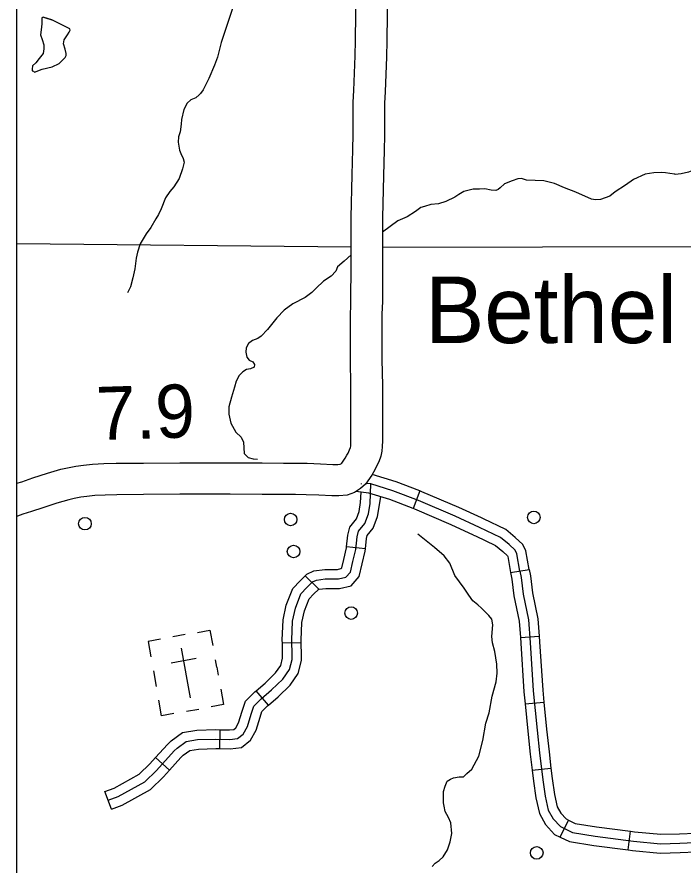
# Model space of a CAD drawing. Extents: x 1369979 to 1371646, y 379997 to 381064.
# Drawn here: x 1370544.5 to 1370606.5, y 380305.4 to 380384.3 of the extents above; entities that cross this region are included whole.
import ezdxf

# ---------------------------------------------------------------- set-up
doc = ezdxf.new("R2010")
doc.units = 0
doc.layers.add('R_Border Notes', color=7, linetype='Continuous')
doc.layers.add('R_No Plot', color=7, linetype='Continuous')

msp = doc.modelspace()

# ---------------------------------------------------------------- linework, layer by layer
at = {"layer": 'R_Border Notes'}
for p, q in [((1370582.009, 380340.244), (1370581.378, 380338.604)), ((1370587.727, 380337.738), (1370587.727, 380337.738)), ((1370576.925, 380334.851), (1370575.178, 380335.045)), ((1370590.426, 380332.649), (1370592.16, 380332.936)), ((1370572.582, 380331.117), (1370571.338, 380332.36)), ((1370560.164, 380326.878), (1370559.011, 380326.668)), ((1370591.353, 380326.621), (1370593.106, 380326.751)), ((1370559.791, 380325.619), (1370560.63, 380321.007)), ((1370570.959, 380326.112), (1370569.202, 380326.079)), ((1370558.847, 380324.256), (1370561.164, 380324.678)), ((1370563.093, 380323.838), (1370562.963, 380324.548)), ((1370563.093, 380323.838), (1370563.226, 380323.107)), ((1370557.199, 380323.499), (1370557.461, 380322.058)), ((1370560.21, 380323.313), (1370560.21, 380323.313)), ((1370560.21, 380323.313), (1370560.21, 380323.313)), ((1370567.903, 380320.309), (1370566.753, 380321.638)), ((1370560.27, 380319.751), (1370561.422, 380319.96)), ((1370591.792, 380320.428), (1370593.542, 380320.601)), ((1370563.374, 380316.276), (1370563.409, 380318.034)), ((1370558.699, 380314.277), (1370557.398, 380315.459)), ((1370592.448, 380314.262), (1370594.195, 380314.462)), ((1370553.286, 380310.639), (1370552.689, 380312.292)), ((1370595.055, 380308.048), (1370595.827, 380309.627)), ((1370601.375, 380306.844), (1370601.604, 380308.586))]:
    msp.add_line(p, q, dxfattribs=at)
for points in [[(1370575.58, 380357.913), (1370575.596, 380361.239), (1370575.604, 380365.69), (1370575.683, 380369.665), (1370575.754, 380372.023), (1370575.792, 380373.399), (1370575.793, 380376.406), (1370575.841, 380377.504), (1370575.974, 380380.734), (1370576.004, 380382.172), (1370576.004, 380382.412), (1370576.068, 380386.386), (1370576.146, 380388.319), (1370576.169, 380389.662), (1370576.177, 380390.743)], [(1370579.107, 380390.722), (1370579.099, 380389.626), (1370579.075, 380388.235), (1370578.997, 380386.303), (1370578.934, 380382.389), (1370578.934, 380382.141), (1370578.902, 380380.642), (1370578.768, 380377.379), (1370578.722, 380376.341), (1370578.722, 380373.358), (1370578.682, 380371.938), (1370578.612, 380369.592), (1370578.534, 380365.658), (1370578.526, 380361.23), (1370578.51, 380357.899)], [(1370565.47, 380387.318), (1370565.127, 380386.498), (1370564.697, 380385.551), (1370564.367, 380384.591), (1370563.852, 380382.999), (1370563.508, 380381.981), (1370563.164, 380380.604), (1370562.877, 380379.873), (1370562.362, 380378.625)], [(1370547.751, 380384.08), (1370546.942, 380384.32), (1370546.799, 380384.262), (1370546.799, 380383.703), (1370546.741, 380383.144), (1370546.698, 380382.671), (1370546.842, 380382.255), (1370546.985, 380381.753), (1370546.999, 380381.394), (1370546.928, 380380.95), (1370546.57, 380380.477), (1370546.24, 380380.075), (1370545.954, 380379.803), (1370545.911, 380379.502), (1370545.911, 380379.329), (1370546.025, 380379.301), (1370546.125, 380379.215), (1370546.842, 380379.487), (1370547.787, 380379.702), (1370548.418, 380380.018), (1370548.976, 380380.577), (1370549.077, 380380.749), (1370549.062, 380380.95), (1370548.976, 380381.337), (1370548.833, 380381.839), (1370548.89, 380382.212), (1370549.191, 380382.671), (1370549.349, 380382.943), (1370549.449, 380383.115), (1370549.42, 380383.244), (1370547.751, 380384.08)], [(1370546.972, 380384.318), (1370547.822, 380384.057), (1370549.384, 380383.276)], [(1370562.362, 380378.625), (1370561.82, 380377.561), (1370561.591, 380377.217), (1370561.462, 380377.117), (1370561.132, 380376.816), (1370560.674, 380376.629), (1370560.33, 380376.342), (1370560.044, 380375.754), (1370559.8, 380374.822), (1370559.771, 380374.364), (1370559.685, 380373.661), (1370559.528, 380373.202), (1370559.499, 380372.686), (1370559.628, 380371.94), (1370559.757, 380371.639), (1370559.972, 380371.194), (1370560.072, 380370.846)], [(1370560.072, 380370.846), (1370559.9, 380370.215), (1370559.599, 380369.326), (1370559.098, 380368.552), (1370558.726, 380368.121), (1370558.324, 380367.519), (1370557.909, 380366.501), (1370557.665, 380365.956), (1370557.436, 380365.569), (1370556.949, 380364.752), (1370556.519, 380364.164), (1370556.247, 380363.705), (1370555.961, 380363.246), (1370555.731, 380362.472)], [(1370611.682, 380369.273), (1370610.276, 380369.406), (1370609.358, 380369.673), (1370608.973, 380369.851), (1370608.485, 380370.206), (1370608.056, 380370.251), (1370607.479, 380370.088), (1370607.02, 380369.895), (1370606.324, 380369.747), (1370605.777, 380369.688), (1370605.732, 380369.732), (1370605.259, 380369.777), (1370604.874, 380369.851), (1370604.474, 380369.866), (1370603.779, 380369.851), (1370602.979, 380369.732), (1370601.899, 380369.229), (1370601.129, 380368.695), (1370600.182, 380368.073), (1370599.694, 380367.688), (1370598.82, 380367.377)], [(1370591.927, 380369.169), (1370591.457, 380369.318), (1370591.117, 380369.273), (1370590.584, 380369.095), (1370589.874, 380368.814), (1370589.459, 380368.444), (1370589.297, 380368.31), (1370589.075, 380368.192), (1370588.645, 380368.221), (1370588.039, 380368.369)], [(1370598.82, 380367.377), (1370598.35, 380367.347), (1370597.965, 380367.407), (1370596.529, 380368.058), (1370595.449, 380368.444), (1370594.546, 380368.843), (1370593.525, 380369.095), (1370591.927, 380369.169)], [(1370588.039, 380368.369), (1370587.552, 380368.325), (1370586.96, 380368.325), (1370586.101, 380368.118), (1370585.613, 380367.821), (1370585.243, 380367.57), (1370584.414, 380367.17), (1370583.733, 380366.962), (1370583.023, 380366.903), (1370582.446, 380366.725), (1370582.09, 380366.607)], [(1370582.09, 380366.607), (1370581.602, 380366.236), (1370580.818, 380365.762), (1370579.959, 380365.377), (1370578.531, 380364.332)], [(1370544.495, 380363.267), (1370575.599, 380362.946)], [(1370555.731, 380362.472), (1370555.602, 380361.912), (1370555.474, 380360.909), (1370555.287, 380360.091), (1370555.058, 380359.245), (1370554.786, 380358.672)], [(1370578.529, 380362.933), (1370608.293, 380362.985)], [(1370575.598, 380362.213), (1370574.946, 380361.62), (1370574.325, 380361.102)], [(1370574.325, 380361.102), (1370574.163, 380360.693), (1370573.749, 380360.234), (1370573.024, 380359.775), (1370572.358, 380359.123), (1370571.929, 380358.708), (1370571.322, 380358.234), (1370570.167, 380357.671), (1370569.368, 380357.064), (1370568.673, 380356.353), (1370567.829, 380355.256)], [(1370575.58, 380350.002), (1370575.541, 380352.467), (1370575.541, 380353.653), (1370575.533, 380355.238), (1370575.541, 380356.153), (1370575.541, 380356.765), (1370575.565, 380357.382), (1370575.581, 380357.946)], [(1370578.509, 380357.866), (1370578.493, 380357.284), (1370578.471, 380356.707), (1370578.471, 380356.14), (1370578.463, 380355.233), (1370578.471, 380353.66), (1370578.471, 380352.49), (1370578.51, 380350.049)], [(1370567.829, 380355.256), (1370567.24, 380354.642), (1370566.914, 380354.434), (1370566.411, 380354.242), (1370566.056, 380353.96), (1370565.834, 380353.575), (1370565.804, 380353.16), (1370565.908, 380352.686), (1370566.1, 380352.427)], [(1370566.1, 380352.427), (1370566.441, 380352.249), (1370566.618, 380352.012), (1370566.589, 380351.76), (1370566.234, 380351.612), (1370565.864, 380351.538), (1370565.523, 380351.319), (1370565.168, 380350.99), (1370564.887, 380350.457), (1370564.754, 380349.909), (1370564.472, 380348.961), (1370564.221, 380348.072), (1370564.206, 380347.39), (1370564.398, 380346.561), (1370564.872, 380345.731), (1370565.36, 380345.242), (1370565.568, 380344.783), (1370565.627, 380344.265)], [(1370578.51, 380350.032), (1370578.518, 380348.18), (1370578.51, 380346.185), (1370578.518, 380344.914), (1370578.5, 380344.385), (1370578.464, 380343.953), (1370578.352, 380343.492), (1370578.178, 380342.97), (1370577.945, 380342.484), (1370577.802, 380342.198), (1370577.538, 380341.724), (1370576.934, 380340.867), (1370576.486, 380340.463), (1370575.907, 380340.095), (1370575.231, 380339.843), (1370574.449, 380339.783), (1370573.817, 380339.792), (1370572.601, 380339.848), (1370571.431, 380339.902), (1370570.413, 380339.917), (1370569.302, 380339.917)], [(1370569.302, 380342.847), (1370570.435, 380342.847), (1370571.521, 380342.83), (1370572.736, 380342.774), (1370573.906, 380342.72), (1370574.358, 380342.714), (1370574.595, 380342.732), (1370574.706, 380342.803), (1370574.729, 380342.823), (1370575.054, 380343.286), (1370575.211, 380343.566), (1370575.313, 380343.771), (1370575.457, 380344.071), (1370575.534, 380344.303), (1370575.563, 380344.423), (1370575.574, 380344.557), (1370575.588, 380344.955), (1370575.58, 380346.181), (1370575.588, 380348.18), (1370575.58, 380350.019)], [(1370565.627, 380344.265), (1370565.656, 380343.724), (1370566.026, 380343.354), (1370566.485, 380343.25), (1370566.9, 380343.206)], [(1370544.495, 380340.971), (1370544.956, 380341.111), (1370545.973, 380341.46), (1370547.345, 380341.902), (1370548.577, 380342.266), (1370549.199, 380342.407), (1370549.983, 380342.562), (1370550.681, 380342.649), (1370551.525, 380342.733), (1370552.573, 380342.791), (1370553.739, 380342.823), (1370556.261, 380342.839), (1370559.648, 380342.87), (1370564.363, 380342.87), (1370567.325, 380342.855), (1370569.308, 380342.847)], [(1370582.009, 380340.244), (1370579.783, 380341.101), (1370577.567, 380341.775)], [(1370559.126, 380316.054), (1370559.413, 380316.329), (1370560.246, 380316.928), (1370561.313, 380317.11), (1370563.004, 380317.163), (1370564.306, 380317.137), (1370565.034, 380317.215), (1370565.555, 380317.631), (1370565.945, 380318.335), (1370566.284, 380319.481), (1370566.536, 380320.218), (1370567.239, 380320.896), (1370568.202, 380321.729), (1370569.243, 380322.745), (1370569.867, 380323.631), (1370570.101, 380324.569), (1370570.101, 380324.954), (1370570.075, 380326.361), (1370570.153, 380328.133), (1370570.414, 380329.357), (1370570.934, 380330.686), (1370571.481, 380331.259), (1370572.001, 380331.78), (1370572.392, 380331.962), (1370573.198, 380332.066), (1370574.422, 380332.066), (1370575.124, 380332.223), (1370575.541, 380332.692), (1370575.775, 380333.681), (1370576.035, 380334.802), (1370576.165, 380335.974), (1370576.295, 380336.495), (1370576.868, 380337.224), (1370577.206, 380338.11), (1370577.362, 380339.074), (1370577.44, 380340.895)], [(1370576.56, 380340.877), (1370576.562, 380340.933)], [(1370591.293, 380332.792), (1370591.026, 380334.408), (1370590.869, 380334.747), (1370590.297, 380335.268), (1370589.516, 380335.919), (1370587.538, 380336.857), (1370585.274, 380337.899), (1370581.865, 380339.358), (1370579.496, 380340.27), (1370577.44, 380340.895), (1370576.994, 380340.952)], [(1370569.296, 380339.917), (1370567.311, 380339.925), (1370564.356, 380339.941), (1370559.661, 380339.941), (1370556.284, 380339.909), (1370553.789, 380339.894), (1370552.695, 380339.863), (1370551.75, 380339.811), (1370551.008, 380339.738), (1370550.45, 380339.668), (1370549.806, 380339.54), (1370549.316, 380339.43), (1370548.21, 380339.103), (1370546.898, 380338.68), (1370545.859, 380338.323), (1370545.046, 380338.076), (1370544.555, 380337.917), (1370544.495, 380337.892)], [(1370575.178, 380335.045), (1370575.298, 380336.13), (1370575.488, 380336.89), (1370576.094, 380337.662), (1370576.353, 380338.34), (1370576.487, 380339.163), (1370576.528, 380340.126)], [(1370581.378, 380338.604), (1370579.21, 380339.438), (1370577.255, 380340.033), (1370576.052, 380340.187)], [(1370576.925, 380334.851), (1370577.032, 380335.818), (1370577.103, 380336.1), (1370577.641, 380336.786), (1370578.059, 380337.881), (1370578.354, 380339.699)], [(1370587.727, 380337.738), (1370585.631, 380338.702), (1370582.196, 380340.172), (1370582.009, 380340.244)], [(1370586.992, 380336.141), (1370584.917, 380337.096), (1370581.534, 380338.544), (1370581.378, 380338.604)], [(1370592.16, 380332.936), (1370591.873, 380334.669), (1370591.593, 380335.277), (1370590.874, 380335.931), (1370589.993, 380336.666), (1370587.91, 380337.653), (1370587.727, 380337.738)], [(1370585.254, 380332.383), (1370584.788, 380333.52), (1370584.255, 380334.226), (1370583.377, 380334.976), (1370581.808, 380336.229)], [(1370586.992, 380336.141), (1370587.166, 380336.061), (1370589.039, 380335.173), (1370589.719, 380334.605), (1370590.146, 380334.217), (1370590.178, 380334.148), (1370590.426, 380332.649)], [(1370571.338, 380332.36), (1370571.489, 380332.51), (1370572.143, 380332.816), (1370573.142, 380332.945), (1370574.325, 380332.945), (1370574.656, 380333.019), (1370574.736, 380333.109), (1370574.919, 380333.882), (1370575.167, 380334.95), (1370575.178, 380335.045)], [(1370572.514, 380331.049), (1370572.64, 380331.108), (1370573.255, 380331.187), (1370574.518, 380331.187), (1370575.593, 380331.426), (1370576.345, 380332.274), (1370576.631, 380333.481), (1370576.903, 380334.653), (1370576.925, 380334.851)], [(1370590.425, 380332.649), (1370590.556, 380332.045), (1370590.751, 380330.495), (1370591.241, 380328.12), (1370591.353, 380326.621)], [(1370591.293, 380332.792), (1370591.423, 380332.193), (1370591.619, 380330.639), (1370592.113, 380328.242), (1370592.27, 380326.147), (1370592.556, 380321.641), (1370592.915, 380318.004), (1370593.149, 380315.868), (1370593.436, 380313.367), (1370593.67, 380311.856), (1370593.956, 380310.553), (1370594.398, 380309.746), (1370595.075, 380309.016), (1370596.194, 380308.469), (1370598.328, 380308.131), (1370601.894, 380307.662), (1370604.392, 380307.427), (1370606.188, 380307.479), (1370608.244, 380307.558)], [(1370592.161, 380332.936), (1370592.29, 380332.342), (1370592.487, 380330.783), (1370592.986, 380328.364), (1370593.106, 380326.751)], [(1370569.202, 380326.079), (1370569.196, 380326.372), (1370569.279, 380328.244), (1370569.569, 380329.61), (1370570.179, 380331.167), (1370570.852, 380331.873), (1370571.338, 380332.36)], [(1370586.112, 380331.2), (1370585.254, 380332.383)], [(1370570.959, 380326.112), (1370570.955, 380326.35), (1370571.028, 380328.021), (1370571.258, 380329.104), (1370571.69, 380330.204), (1370572.11, 380330.645), (1370572.582, 380331.117)], [(1370588.992, 380325.321), (1370588.747, 380326.105), (1370588.689, 380326.696), (1370588.804, 380327.777), (1370588.704, 380328.31), (1370588.416, 380328.67), (1370588.07, 380329.016), (1370587.739, 380329.347), (1370587.394, 380329.65), (1370586.933, 380330.01), (1370586.559, 380330.538), (1370586.112, 380331.2)], [(1370561.31, 380327.087), (1370562.463, 380327.297), (1370562.725, 380325.855)], [(1370557.851, 380326.457), (1370556.698, 380326.247), (1370556.961, 380324.806)], [(1370591.353, 380326.621), (1370591.393, 380326.087), (1370591.68, 380321.57), (1370591.792, 380320.428)], [(1370593.106, 380326.751), (1370593.146, 380326.208), (1370593.432, 380321.712), (1370593.542, 380320.601)], [(1370566.753, 380321.638), (1370567.607, 380322.377), (1370568.571, 380323.318), (1370569.054, 380324.003), (1370569.223, 380324.677), (1370569.223, 380324.946), (1370569.202, 380326.079)], [(1370567.903, 380320.309), (1370568.797, 380321.082), (1370569.914, 380322.173), (1370570.68, 380323.259), (1370570.98, 380324.461), (1370570.98, 380324.963), (1370570.959, 380326.112)], [(1370588.142, 380318.628), (1370588.444, 380319.601), (1370588.732, 380321.157), (1370589.092, 380322.482), (1370589.193, 380323.304), (1370589.164, 380324.14), (1370588.992, 380325.321)], [(1370563.46, 380321.82), (1370563.722, 380320.379), (1370562.569, 380320.169)], [(1370563.409, 380318.034), (1370564.267, 380318.016), (1370564.685, 380318.061), (1370564.87, 380318.209), (1370565.13, 380318.677), (1370565.446, 380319.748), (1370565.773, 380320.704), (1370566.646, 380321.545), (1370566.753, 380321.638)], [(1370559.11, 380319.54), (1370557.957, 380319.33), (1370557.695, 380320.771)], [(1370563.374, 380316.276), (1370564.344, 380316.257), (1370565.383, 380316.368), (1370566.239, 380317.054), (1370566.761, 380317.993), (1370567.121, 380319.214), (1370567.299, 380319.733), (1370567.832, 380320.247), (1370567.903, 380320.309)], [(1370591.792, 380320.428), (1370592.041, 380317.913), (1370592.276, 380315.77), (1370592.448, 380314.262)], [(1370593.542, 380320.601), (1370593.789, 380318.095), (1370594.023, 380315.966), (1370594.195, 380314.462)], [(1370584.845, 380313.426), (1370585.133, 380313.556), (1370585.666, 380313.642), (1370586.055, 380313.657), (1370586.371, 380313.945), (1370586.847, 380314.363), (1370587.494, 380315.573), (1370587.854, 380317.043), (1370588.142, 380318.628)], [(1370557.398, 380315.459), (1370558.496, 380316.667), (1370558.849, 380317.006), (1370559.897, 380317.76), (1370561.225, 380317.987), (1370563, 380318.042), (1370563.409, 380318.034)], [(1370552.987, 380311.465), (1370553.924, 380311.804), (1370556.397, 380313.185), (1370557.49, 380314.253), (1370559.126, 380316.054)], [(1370558.699, 380314.277), (1370559.756, 380315.44), (1370559.977, 380315.652), (1370560.594, 380316.096), (1370561.401, 380316.234), (1370563.009, 380316.283), (1370563.374, 380316.276)], [(1370552.689, 380312.292), (1370553.558, 380312.606), (1370555.866, 380313.895), (1370556.857, 380314.863), (1370557.398, 380315.459)], [(1370594.195, 380314.462), (1370594.307, 380313.484), (1370594.534, 380312.018), (1370594.787, 380310.865), (1370595.117, 380310.264), (1370595.608, 380309.734), (1370595.827, 380309.627)], [(1370553.286, 380310.639), (1370554.29, 380311.002), (1370556.927, 380312.474), (1370558.123, 380313.642), (1370558.699, 380314.277)], [(1370592.448, 380314.262), (1370592.564, 380313.25), (1370592.805, 380311.694), (1370593.125, 380310.242), (1370593.68, 380309.228), (1370594.542, 380308.299), (1370595.055, 380308.048)], [(1370584.817, 380307.591), (1370584.989, 380308.375), (1370584.874, 380309.37), (1370584.658, 380309.86), (1370584.37, 380310.422), (1370584.255, 380310.926), (1370584.198, 380311.243), (1370584.198, 380311.848), (1370584.198, 380312.28), (1370584.342, 380312.77), (1370584.543, 380313.231), (1370584.845, 380313.426)], [(1370595.827, 380309.627), (1370596.462, 380309.317), (1370598.454, 380309.001), (1370601.604, 380308.586)], [(1370595.055, 380308.048), (1370595.926, 380307.622), (1370598.202, 380307.261), (1370601.375, 380306.844)], [(1370601.604, 380308.586), (1370601.992, 380308.535), (1370604.42, 380308.307), (1370606.158, 380308.358), (1370607.628, 380308.414)], [(1370583.147, 380305.3), (1370583.42, 380305.617), (1370583.795, 380305.877), (1370584.183, 380306.208), (1370584.586, 380306.842), (1370584.817, 380307.591)], [(1370601.375, 380306.844), (1370601.795, 380306.788), (1370604.364, 380306.547), (1370606.217, 380306.601), (1370607.694, 380306.657)]]:
    msp.add_lwpolyline(points, dxfattribs=at)
for centre in [(1370569.971, 380337.594), (1370592.61, 380337.783), (1370550.82, 380337.204), (1370570.245, 380334.612), (1370575.603, 380328.888), (1370592.878, 380306.575)]:
    msp.add_circle(centre, 0.586, dxfattribs=at)
at = {"layer": 'R_No Plot'}
msp.add_lwpolyline([(1370544.495, 380586.867), (1371140.383, 380586.867), (1371140.383, 380146.391), (1370544.495, 380146.391)], close=True, dxfattribs=at)

# ---------------------------------------------------------------- texts
at = {"layer": 'R_Border Notes'}
msp.add_text('Bethel', height=6.1875, dxfattribs=at).set_placement((1370582.478, 380354.006))
msp.add_text('7.9', height=4.95, rotation=1.79158, dxfattribs=at).set_placement((1370551.931, 380344.969))

doc.saveas('drawing.dxf')
